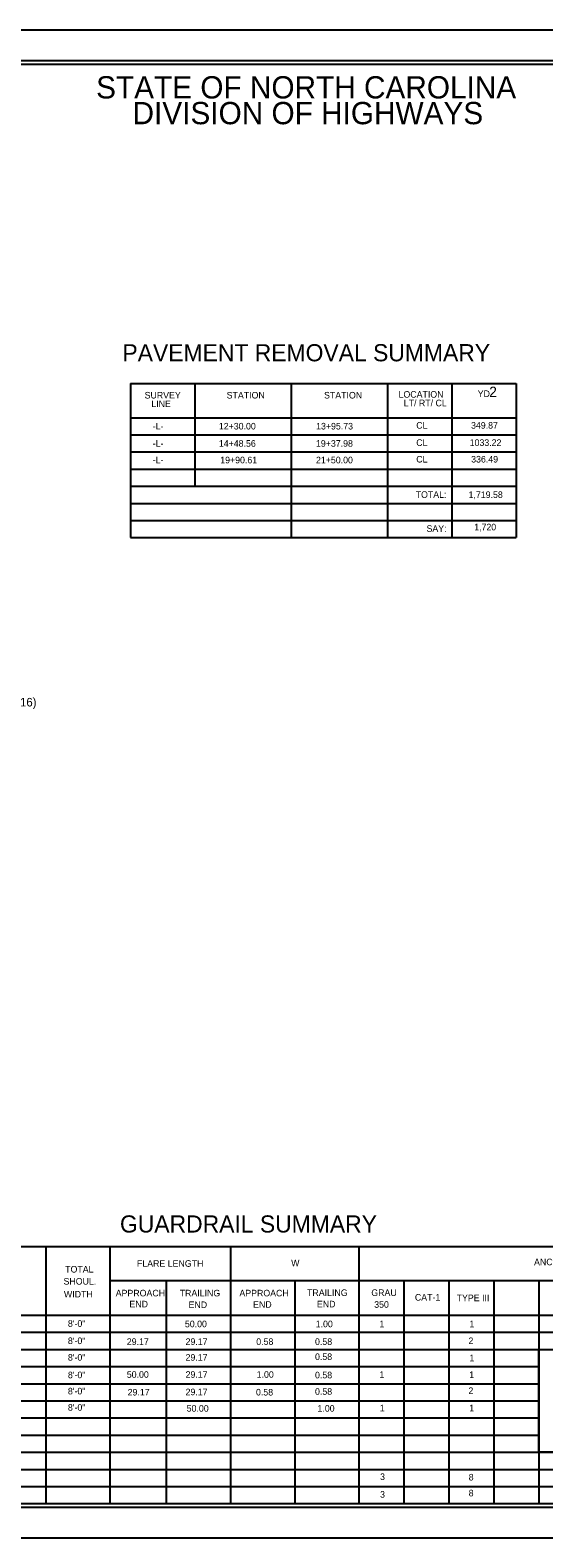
# Model space of a CAD drawing. Extents: x 1728103 to 1731948, y 539631 to 540733.
# Drawn here: x 1731005 to 1731380, y 539631 to 540731 of the extents above; entities that cross this region are included whole.
import ezdxf

# ---------------------------------------------------------------- set-up
doc = ezdxf.new("R2010")
doc.units = 0
for name, color, linetype in [('Sheet Cutting Line CELL', 7, 'Continuous'), ('Sheet Plot Border Inside CELL', 7, 'Continuous'), ('Sheet Plot Border Outside CELL', 7, 'Continuous'), ('Sheet Summary Combination CELL', 7, 'Continuous'), ('Sheet Summary Combination Grid CELL', 7, 'Continuous')]:
    doc.layers.add(name, color=color, linetype=linetype)

msp = doc.modelspace()

# ---------------------------------------------------------------- linework, layer by layer
at = {"layer": 'Sheet Cutting Line CELL'}
for p, q in [((1731947.7, 540730.8), (1730263.7, 540730.8)), ((1730263.7, 539630.8), (1731947.7, 539630.8))]:
    msp.add_line(p, q, dxfattribs=at)
at = {"layer": 'Sheet Plot Border Inside CELL'}
msp.add_lwpolyline([(1731943.2, 540708.4), (1730276.7, 540708.4), (1730276.7, 539653.3), (1731943.2, 539653.3)], close=True, dxfattribs=at)
at = {"layer": 'Sheet Plot Border Outside CELL'}
msp.add_lwpolyline([(1731947.7, 540730.8), (1730263.7, 540730.8), (1730263.7, 539630.8), (1731947.7, 539630.8)], close=True, dxfattribs=at)
at = {"layer": 'Sheet Summary Combination CELL'}
for p, q in [((1731220, 540473.1), (1731220, 540473.1)), ((1731226.2, 540473), (1731226.2, 540473)), ((1731235.3, 540473.2), (1731235.3, 540473.2)), ((1731240.9, 540473.1), (1731240.9, 540473.1))]:
    msp.add_line(p, q, dxfattribs=at)
msp.add_lwpolyline([(1731930.7, 540705.8), (1730430.7, 540705.8), (1730430.7, 539655.8), (1731930.7, 539655.8)], close=True, dxfattribs=at)
at = {"layer": 'Sheet Summary Combination Grid CELL'}
for p, q in [((1731078.7, 540473.1), (1731360.1, 540473.1)), ((1731078.7, 540473.1), (1731078.7, 540360.6)), ((1731125.6, 540473.1), (1731125.6, 540398.1)), ((1731196, 540473.1), (1731196, 540360.6)), ((1731266.3, 540473.1), (1731266.3, 540360.6)), ((1731313.2, 540473.1), (1731313.2, 540360.6)), ((1731360.1, 540473.1), (1731360.1, 540360.6)), ((1731078.7, 540448.1), (1731360.1, 540448.1)), ((1731078.7, 540435.6), (1731360.1, 540435.6)), ((1731078.7, 540423.1), (1731360.1, 540423.1)), ((1731078.7, 540410.6), (1731360.1, 540410.6)), ((1731078.7, 540398.1), (1731360.1, 540398.1)), ((1731078.7, 540385.6), (1731360.1, 540385.6)), ((1731078.7, 540373.1), (1731360.1, 540373.1)), ((1731078.7, 540360.6), (1731360.1, 540360.6)), ((1730430.7, 539843.3), (1731930.7, 539843.3)), ((1731016.7, 539843.3), (1731016.7, 539655.8)), ((1731063.5, 539843.3), (1731063.5, 539655.8)), ((1731151.6, 539843.3), (1731151.6, 539655.8)), ((1731245.4, 539843.3), (1731245.4, 539655.8)), ((1731540.7, 539818.3), (1731063.5, 539818.3)), ((1731104.7, 539818.3), (1731104.7, 539655.8)), ((1731198.5, 539818.3), (1731198.5, 539655.8)), ((1731278.2, 539818.3), (1731278.2, 539655.8)), ((1731311, 539818.3), (1731311, 539655.8)), ((1731343.8, 539818.3), (1731343.8, 539655.8)), ((1731376.6, 539818.3), (1731376.6, 539655.8)), ((1730430.7, 539793.3), (1731930.7, 539793.3)), ((1730430.7, 539780.8), (1731930.7, 539780.8)), ((1730430.7, 539768.3), (1731930.7, 539768.3)), ((1730430.7, 539755.8), (1731376.6, 539755.8)), ((1730430.7, 539743.3), (1731376.6, 539743.3)), ((1730430.7, 539730.8), (1731376.6, 539730.8)), ((1730430.7, 539718.3), (1731376.6, 539718.3)), ((1730430.7, 539705.8), (1731376.6, 539705.8)), ((1730430.7, 539693.3), (1731930.7, 539693.3)), ((1730430.7, 539680.8), (1731930.7, 539680.8)), ((1730430.7, 539668.3), (1731930.7, 539668.3))]:
    msp.add_line(p, q, dxfattribs=at)
msp.add_lwpolyline([(1731376.6, 539768.3), (1731508, 539768.3), (1731508, 539693.3), (1731376.6, 539693.3)], close=True, dxfattribs=at)

# ---------------------------------------------------------------- texts
at = {"layer": 'Sheet Summary Combination CELL'}
for s, height, p in [('STATE OF NORTH CAROLINA', 16.25, (1731053.5, 540681)), ('DIVISION OF HIGHWAYS', 16.25, (1731080.1, 540662.2)), ('SURVEY', 4.8, (1731088.9, 540462.1)), ('STATION', 4.8, (1731148.8, 540462.1)), ('STATION', 4.8, (1731219.9, 540462.1)), ('LOCATION', 4.8, (1731274.3, 540462.7)), ('LINE', 4.8, (1731093.8, 540455.8)), ('LT/ RT/ CL', 4.8, (1731278.1, 540456.4)), ('-L-', 4.8, (1731094.8, 540439.5)), ('12+30.00', 4.8, (1731143.1, 540439.5)), ('13+95.73', 4.8, (1731214.1, 540439.5)), ('CL', 4.8, (1731287.2, 540440.1)), ('349.87', 4.8, (1731327.2, 540440.1)), ('-L-', 4.8, (1731094.8, 540426.9)), ('14+48.56', 4.8, (1731143.1, 540426.9)), ('19+37.98', 4.8, (1731214, 540426.9)), ('CL', 4.8, (1731287.2, 540427.5)), ('1033.22', 4.8, (1731326.2, 540427.5)), ('-L-', 4.8, (1731094.8, 540414.8)), ('19+90.61', 4.8, (1731144.1, 540414.8)), ('21+50.00', 4.8, (1731214, 540414.8)), ('CL', 4.8, (1731287.2, 540415.4)), ('336.49', 4.8, (1731327.3, 540415.4)), ('TOTAL:', 4.8, (1731286.8, 540389.6)), ('1,719.58', 4.8, (1731325.4, 540389.5)), ('SAY:', 4.8, (1731294.7, 540364.8)), ('1,720', 4.8, (1731329.5, 540365.9)), ('EST SELECT GRANULAR MATERIAL = 400 CY CONTINGENCY (FROM GEOTECH RECS. DATED 6-2-16)', 6.25, (1730603.4, 540237.4)), ('GUARDRAIL SUMMARY', 12.5, (1731070.9, 539853.6)), ('TOTAL', 4.8, (1731030.9, 539824.4)), ('FLARE LENGTH', 4.8, (1731083.3, 539828.6)), ('W', 4.8, (1731195.9, 539829)), ('ANCHORS', 4.8, (1731373.2, 539829.7)), ('SHOUL.', 4.8, (1731029.7, 539815.6)), ('WIDTH', 4.8, (1731030, 539806.2)), ('APPROACH', 4.8, (1731067.8, 539807)), ('END', 4.8, (1731077.8, 539799)), ('TRAILING', 4.8, (1731114.5, 539807)), ('END', 4.8, (1731121, 539798.5)), ('APPROACH', 4.8, (1731158.1, 539807)), ('END', 4.8, (1731168.1, 539798.7)), ('TRAILING', 4.8, (1731207.5, 539807.3)), ('END', 4.8, (1731214.7, 539799)), ('GRAU', 4.8, (1731254.4, 539807.3)), ('350', 4.8, (1731256.5, 539798.7)), ('CAT-1', 4.8, (1731286.2, 539803.9)), ('TYPE III', 4.8, (1731316.7, 539803.5)), ('8\'-0"', 4.8, (1731032.9, 539784.8)), ('50.00', 4.8, (1731118.3, 539784.5)), ('1.00', 4.8, (1731213.8, 539784.5)), ('1', 4.8, (1731260.3, 539784.5)), ('1', 4.8, (1731326, 539784.5)), ('8\'-0"', 4.8, (1731032.9, 539772.2)), ('29.17', 4.8, (1731075.9, 539771.6)), ('29.17', 4.8, (1731118.8, 539771.6)), ('0.58', 4.8, (1731170.4, 539771.6)), ('0.58', 4.8, (1731213.3, 539771.6)), ('2', 4.8, (1731325.3, 539772.2)), ('8\'-0"', 4.8, (1731032.9, 539760.1)), ('29.17', 4.8, (1731118.8, 539760.1)), ('0.58', 4.8, (1731213.3, 539760.6)), ('1', 4.8, (1731326, 539759.7)), ('8\'-0"', 4.8, (1731032.9, 539747.3)), ('50.00', 4.8, (1731075.9, 539747.6)), ('29.17', 4.8, (1731118.8, 539747.6)), ('1.00', 4.8, (1731170.7, 539747.6)), ('0.58', 4.8, (1731213.3, 539747.2)), ('1', 4.8, (1731260.3, 539747.5)), ('1', 4.8, (1731325.9, 539747.5)), ('8\'-0"', 4.8, (1731032.9, 539735.5)), ('29.17', 4.8, (1731076.5, 539734.7)), ('29.17', 4.8, (1731118.8, 539734.9)), ('0.58', 4.8, (1731170.2, 539734.7)), ('0.58', 4.8, (1731213.3, 539735.2)), ('2', 4.8, (1731325.3, 539735.8)), ('8\'-0"', 4.8, (1731032.9, 539723.6)), ('50.00', 4.8, (1731119.6, 539722.9)), ('1.00', 4.8, (1731215.1, 539722.9)), ('1', 4.8, (1731260.6, 539723.2)), ('1', 4.8, (1731325.9, 539723.2)), ('3', 4.8, (1731260.8, 539673)), ('8', 4.8, (1731325.5, 539672.7)), ('3', 4.8, (1731260.8, 539660.1)), ('8', 4.8, (1731325.5, 539661.1))]:
    msp.add_text(s, height=height, dxfattribs=at).set_placement(p)
msp.add_text('PAVEMENT REMOVAL SUMMARY', height=12.5, rotation=0.0119, dxfattribs=at).set_placement((1731072.7, 540489.2))
at = {"layer": 'Sheet Summary Combination Grid CELL'}
for s, height, p in [('YD', 4.8, (1731332.1, 540463.2)), ('2', 7.5, (1731340.5, 540463.2))]:
    msp.add_text(s, height=height, dxfattribs=at).set_placement(p)

doc.saveas('drawing.dxf')
